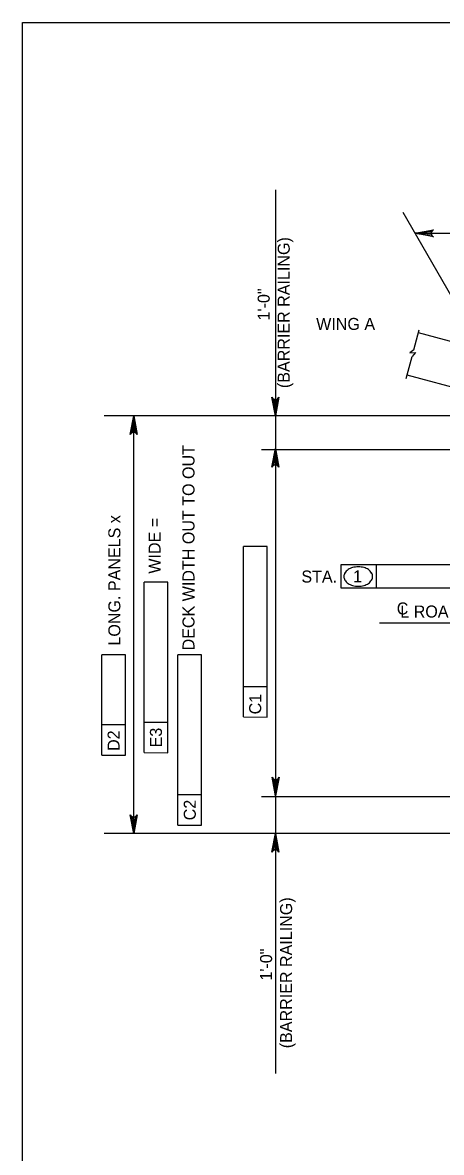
# Model space of a CAD drawing. Extents: x 638268 to 640277, y 295465 to 298435.
# Drawn here: x 639316.5 to 639421, y 296950.5 to 297232.5 of the extents above; entities that cross this region are included whole.
import ezdxf

# ---------------------------------------------------------------- set-up
doc = ezdxf.new("R2010")
doc.units = 0
for name, color, linetype in [('2', 7, 'Continuous'), ('3', 7, 'Continuous'), ('4', 7, 'Continuous')]:
    doc.layers.add(name, color=color, linetype=linetype)

msp = doc.modelspace()

# ---------------------------------------------------------------- linework, layer by layer
at = {"layer": '2'}
for p, q in [((639316.46, 296668.46), (639316.46, 297232.46)), ((639316.46, 297232.46), (640102.46, 297232.46)), ((639438.09, 297148.88), (639415.21, 297155.01)), ((639429.07, 297140), (639412.39, 297144.47))]:
    msp.add_line(p, q, dxfattribs=at)
at = {"layer": '3'}
for p, q in [((639414.07, 297150.76), (639415.41, 297155.76)), ((639412.17, 297143.66), (639413.63, 297149.13)), ((639414.07, 297150.76), (639413.05, 297149.99)), ((639413.05, 297149.99), (639414.51, 297150.08)), ((639414.51, 297150.08), (639413.63, 297149.13))]:
    msp.add_line(p, q, dxfattribs=at)
at = {"layer": '4'}
for p, q in [((639379.56, 297190.71), (639379.56, 296970.18)), ((639508.5, 297016.85), (639411.4, 297185.03)), ((639414.36, 297179.9), (639593.8, 297179.9)), ((639432.73, 297134.29), (639336.8, 297134.29)), ((639344.21, 297030.06), (639344.21, 297134.29)), ((639442, 297125.83), (639376.05, 297125.83)), ((639371.54, 297059.14), (639371.54, 297101.66)), ((639377.45, 297101.66), (639371.54, 297101.66)), ((639377.45, 297059.13), (639377.45, 297101.66)), ((639395.98, 297097.16), (639438.5, 297097.16)), ((639395.98, 297091.26), (639395.98, 297097.16)), ((639404.73, 297091.26), (639404.73, 297097.16)), ((639346.76, 297050.24), (639346.76, 297092.76)), ((639352.67, 297092.75), (639346.76, 297092.76)), ((639352.67, 297050.23), (639352.67, 297092.75)), ((639438.5, 297091.26), (639395.98, 297091.26)), ((639707.69, 297082.58), (639405.47, 297082.58)), ((639336.2, 297049.58), (639336.2, 297074.63)), ((639342.11, 297074.62), (639336.2, 297074.63)), ((639342.11, 297049.57), (639342.11, 297074.62)), ((639355.22, 297032.16), (639355.22, 297074.68)), ((639361.13, 297074.68), (639355.22, 297074.68)), ((639361.13, 297032.16), (639361.13, 297074.68)), ((639377.45, 297066.7), (639371.54, 297066.7)), ((639371.54, 297059.14), (639377.45, 297059.13)), ((639342.11, 297057.14), (639336.2, 297057.14)), ((639352.67, 297057.8), (639346.76, 297057.8)), ((639336.2, 297049.58), (639342.11, 297049.57)), ((639346.76, 297050.24), (639352.67, 297050.23)), ((639361.13, 297039.72), (639355.22, 297039.72)), ((639498.57, 297039.18), (639376.05, 297039.18)), ((639355.22, 297032.16), (639361.13, 297032.16)), ((639488.89, 297030.06), (639336.8, 297030.06))]:
    msp.add_line(p, q, dxfattribs=at)
for points in [[(639414.36, 297179.9), (639419.02, 297180.77), (639418.66, 297180.52), (639418.48, 297180.21), (639418.42, 297179.9), (639418.48, 297179.59), (639418.66, 297179.27), (639419.02, 297179.02), (639414.36, 297179.9), (639418.66, 297179.27), (639418.48, 297179.59), (639414.36, 297179.9), (639418.42, 297179.9), (639418.48, 297180.21), (639414.36, 297179.9), (639418.66, 297180.52)], [(639379.56, 297134.29), (639378.68, 297138.95), (639378.93, 297138.59), (639379.24, 297138.4), (639379.56, 297138.35), (639379.87, 297138.4), (639380.18, 297138.59), (639380.43, 297138.95), (639379.56, 297134.29), (639380.18, 297138.59), (639379.87, 297138.4), (639379.56, 297134.29), (639379.56, 297138.35), (639379.24, 297138.4), (639379.56, 297134.29), (639378.93, 297138.59)], [(639344.21, 297134.29), (639345.08, 297129.63), (639344.83, 297129.98), (639344.52, 297130.17), (639344.21, 297130.22), (639343.9, 297130.17), (639343.58, 297129.98), (639343.33, 297129.63), (639344.21, 297134.29), (639343.58, 297129.98), (639343.9, 297130.17), (639344.21, 297134.29), (639344.21, 297130.22), (639344.52, 297130.17), (639344.21, 297134.29), (639344.83, 297129.98)], [(639379.56, 297126.13), (639380.43, 297121.47), (639380.18, 297121.83), (639379.87, 297122.01), (639379.56, 297122.07), (639379.24, 297122.01), (639378.93, 297121.83), (639378.68, 297121.47), (639379.56, 297126.13), (639378.93, 297121.83), (639379.24, 297122.01), (639379.56, 297126.13), (639379.56, 297122.07), (639379.87, 297122.01), (639379.56, 297126.13), (639380.18, 297121.83)], [(639379.6, 297039.43), (639378.72, 297044.09), (639378.97, 297043.73), (639379.28, 297043.55), (639379.6, 297043.49), (639379.91, 297043.55), (639380.22, 297043.73), (639380.47, 297044.09), (639379.6, 297039.43), (639380.22, 297043.73), (639379.91, 297043.55), (639379.6, 297039.43), (639379.6, 297043.49), (639379.28, 297043.55), (639379.6, 297039.43), (639378.97, 297043.73)], [(639344.21, 297030.06), (639343.33, 297034.72), (639343.58, 297034.36), (639343.9, 297034.18), (639344.21, 297034.12), (639344.52, 297034.18), (639344.83, 297034.36), (639345.08, 297034.72), (639344.21, 297030.06), (639344.83, 297034.36), (639344.52, 297034.18), (639344.21, 297030.06), (639344.21, 297034.12), (639343.9, 297034.18), (639344.21, 297030.06), (639343.58, 297034.36)], [(639379.56, 297030.06), (639380.43, 297025.4), (639380.18, 297025.76), (639379.87, 297025.95), (639379.56, 297026), (639379.24, 297025.95), (639378.93, 297025.76), (639378.68, 297025.4), (639379.56, 297030.06), (639378.93, 297025.76), (639379.24, 297025.95), (639379.56, 297030.06), (639379.56, 297026), (639379.87, 297025.95), (639379.56, 297030.06), (639380.18, 297025.76)]]:
    msp.add_lwpolyline(points, dxfattribs=at)
for points in [[(639343.73, 297131.45), (639344.68, 297131.45), (639344.21, 297134.29)], [(639343.73, 297032.9), (639344.68, 297032.9), (639344.21, 297030.06)]]:
    msp.add_lwpolyline(points, close=True, dxfattribs=at)
for centre, radius, start, end in [((639399.22, 297093.64), 2.75, 124.109, 148.5507), ((639399.82, 297092.75), 3.82, 105.6708, 124.109), ((639400.22, 297091.35), 5.27, 90, 105.6708), ((639400.22, 297091.35), 5.27, 74.3292, 90), ((639400.61, 297092.75), 3.82, 55.891, 74.3292), ((639401.21, 297093.64), 2.75, 31.4493, 55.891), ((639398.31, 297094.2), 1.68, 148.5507, 180), ((639398.31, 297094.2), 1.68, 180, 211.4493), ((639399.22, 297094.76), 2.75, 211.4493, 235.891), ((639401.21, 297094.76), 2.75, 304.109, 328.5507), ((639402.12, 297094.2), 1.68, 0, 31.4493), ((639402.12, 297094.2), 1.68, 328.5507, 0), ((639399.82, 297095.64), 3.82, 235.891, 254.3292), ((639400.22, 297097.04), 5.27, 254.3292, 270), ((639400.22, 297097.04), 5.27, 270, 285.6708), ((639400.61, 297095.64), 3.82, 285.6708, 304.109)]:
    msp.add_arc(centre, radius, start, end, dxfattribs=at)

# ---------------------------------------------------------------- texts
for s, rotation, p in [('(BARRIER RAILING)', 90, (639383.11, 297141.23)), ('1\'-0"', 90, (639378.11, 297158.12)), ('DECK WIDTH OUT TO OUT', 90, (639359.35, 297075.75)), ('LONG. PANELS x', 90, (639340.85, 297076.96)), ('WIDE =', 90, (639350.89, 297094.91)), ('C1', 89.9382, (639375.99, 297059.79)), ('E3', 89.9382, (639351.22, 297051.55)), ('D2', 89.9382, (639340.66, 297050.66)), ('C2', 89.9382, (639359.67, 297033.34)), ('(BARRIER RAILING)', 90, (639383.71, 296976.45)), ('1\'-0"', 90, (639378.71, 296993.34))]:
    msp.add_text(s, height=3, rotation=rotation, dxfattribs=at).set_placement(p)
for s, p in [('WING A', (639389.71, 297155.74)), ('STA.', (639386.02, 297092.69)), ('1', (639398.92, 297092.74)), ('C', (639409.81, 297084.72)), ('L ROADWAY', (639410.7, 297083.96))]:
    msp.add_text(s, height=3, dxfattribs=at).set_placement(p)

doc.saveas('drawing.dxf')
